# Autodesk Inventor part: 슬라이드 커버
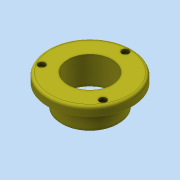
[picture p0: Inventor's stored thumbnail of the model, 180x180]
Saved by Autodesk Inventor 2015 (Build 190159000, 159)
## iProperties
Created: 2015-10
Part Number: 슬라이드 커버
Document SubType Name: Modeling
Designer: mdu
Density: 7.86 g/cm^3
Material: 강철, 연강
Mass: 598.523 g
Surface Area: 229.996 cm^2
Volume: 76.148 cm^3
Appearance: 밝은 황색
Author: mdu
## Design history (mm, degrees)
sketch "스케치1"
  geometry: C1 r 47.5 at (0, 0); C2 r 32.5 at (0, 0); 1 further point
  constraints: 2 centre point, 2 coincident
  dimensions: "d33" = 95 diameter of C1; "d35" = 65 diameter of C2
extrude "돌출1" new body sketch "스케치1" distance "d0" = 10; taper "d1" = 0 deg
extrude "돌출2" join sketch "스케치1" distance "d2" = 25; taper "d3" = 0 deg
hole "구멍1" diameter "d6" = 50; stored, may be unused: countersink angle "d10" = 90 deg, drill point angle "d12" = 118 deg; dims "d4" = 10, "d5" = 10, "d7" = 6, "d8" = 4, "d9" = 2, "d11" = 8
sketch "스케치2" dims "d36" = 80
  geometry: 4 further points
  constraints: 2 coincident, 2 vertical alignment, 2 other
hole "구멍2" sketch "스케치2" at (0, 40) diameter "d13" = 4.5; stored, may be unused: countersink angle "d17" = 90 deg, drill point angle "d19" = 118 deg; dims "d14" = 6, "d15" = 8, "d16" = 4.4, "d18" = 8
fillet "모깎기1" dims "d23" = 3
chamfer "모따기1" distance "d24" = 1; stored, may be unused: second distance "d25" = 2, angle "d26" = 45 deg
sketch "스케치3"
  geometry: C1 r 25 at (0, 0); C2 r 30 at (0, 0); C3 r 26 at (0, 0) reference; 1 further point
  constraints: 2 centre point, 2 coincident
  dimensions: "d27" = 60 diameter of C2
extrude "돌출3" cut sketch "스케치3" distance "d28" = 3; taper "d29" = 0 deg
chamfer "모따기2" distance "d30" = 1; stored, may be unused: second distance "d31" = 2, angle "d32" = 45 deg
node "솔리드1"
pattern_circular "원형 패턴1" dims angle "d21" = 360 deg
